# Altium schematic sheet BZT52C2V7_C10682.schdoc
size 127 x 101 mm
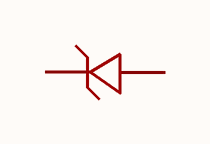
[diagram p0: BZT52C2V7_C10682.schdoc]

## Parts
ZD?  bzt52c2v7_c10682  [SOD-123_L2.8-W1.8-LS3.7-RD]  (value not drawn)

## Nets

Not connected (* = marked no-connect by the designer): ZD? 1(K) 2(A)

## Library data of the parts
ZD? = bzt52c2v7_c10682: 二极管配置:1个独立式;稳压值(标称值):2.7V;稳压值(范围值):2.5V~2.9V;耗散功率(Pd):500mW;; Manufacturer: CJ(江苏长电/长晶); AddInBom: yes; ModelId: 7884390a25fb4c08947731ebfba7e3f8; ModelTransform: 144.8816,62.992,0,0,0,0,0,0,0; Diode Configuration: 1个独立式; Zener Voltage(Nom): 2.7V; Reverse Leakage Current (Ir): 20uA; Pd - Power Dissipation: 500mW; Impedance(Zzt): 100Ω; Impedance(Zzk): 600Ω; Operating Junction Temperature Range: -55℃~+150℃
